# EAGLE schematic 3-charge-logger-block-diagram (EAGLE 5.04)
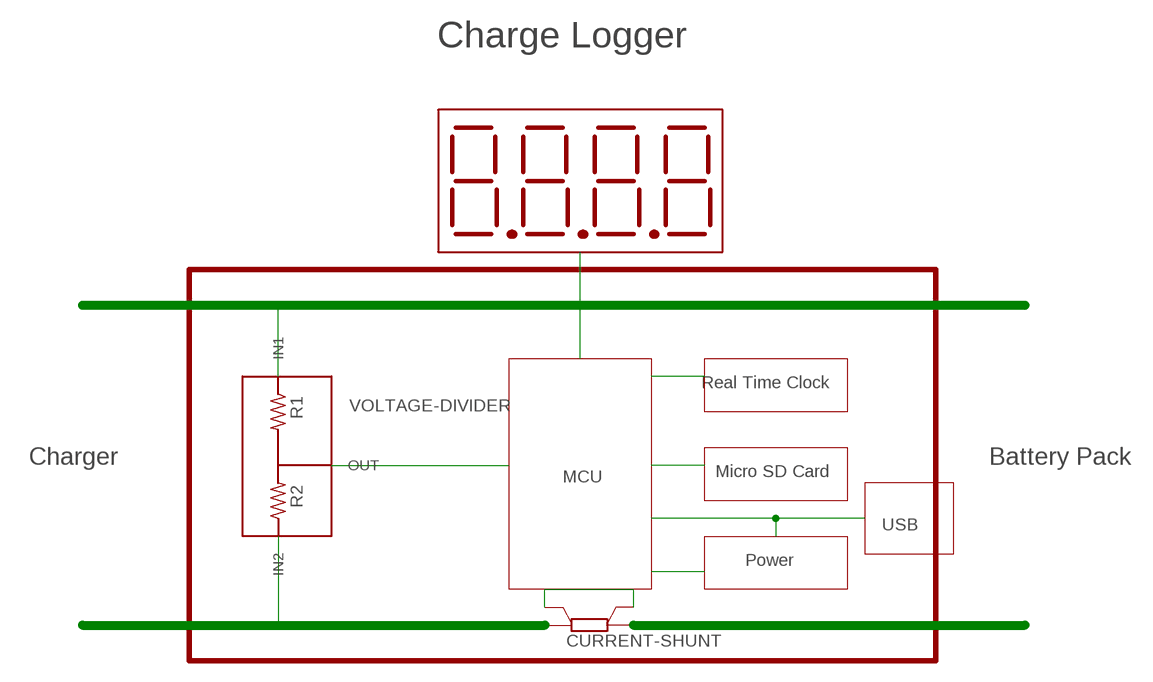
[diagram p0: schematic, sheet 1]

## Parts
CURRENT-SHUNT  SMV  [SMV]
VOLTAGE-DIVIDER  VOLTAGE-DIVIDER  [3TRI]

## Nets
N$1: CURRENT-SHUNT.I1(A) CURRENT-SHUNT.I2(B) VOLTAGE-DIVIDER.P$1(IN1)
N$2: CURRENT-SHUNT.U1(SA) CURRENT-SHUNT.U2(SB)
N$3: VOLTAGE-DIVIDER.P$3(OUT)
N$5: VOLTAGE-DIVIDER.P$2(IN2)

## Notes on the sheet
- Charge Logger
- Real Time Clock
- Charger | Battery Pack
- Micro SD Card
- MCU
- USB
- Power

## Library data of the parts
CURRENT-SHUNT = resistor-shunt:SMV: SMD SHUNT RESISTOR
VOLTAGE-DIVIDER = trl:VOLTAGE-DIVIDER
